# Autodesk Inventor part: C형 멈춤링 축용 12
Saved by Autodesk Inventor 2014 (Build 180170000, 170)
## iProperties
Created: 2026-08
Part Number: C형 멈춤링 축용 12
Material: 일반
Document SubType Name: Modeling
Designer: dg
Density: 1 g/cm^3
Appearance: 기본값
Author: dg
Author: jhkim
Description: 리테이닝 링(C형)
Creation Date: 2026-07-31
Sending System: Autodesk Inventor 2027
Preprocessor: ST-DEVELOPER v20.1
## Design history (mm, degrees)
node "C형 멈춤링 축용 121"
body "Solid1"
node "기준1"
